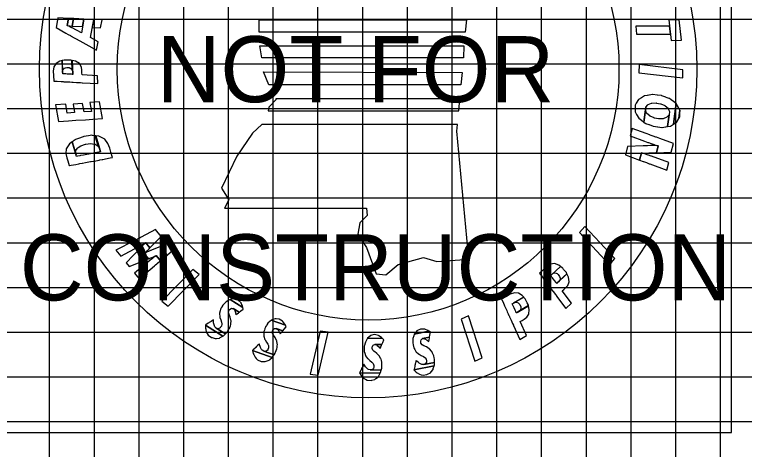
# Model space of a CAD drawing. Extents: x -10 to 342, y -5 to 215.
# Drawn here: x 313.22 to 329.53, y 185.38 to 195.1 of the extents above; entities that cross this region are included whole.
import ezdxf

# ---------------------------------------------------------------- set-up
doc = ezdxf.new("R2010")
doc.units = 0
for name, color, linetype in [('SHEET_LOGO', 7, 'Continuous'), ('SHEET_PRELIM', 7, 'Continuous'), ('XS_SHEET_MAJOR_GRIDS', 7, 'Continuous'), ('XS_SHEET_MEDIUM_GRIDS', 7, 'Continuous'), ('XS_SHEET_MINOR_GRIDS', 7, 'Continuous')]:
    doc.layers.add(name, color=color, linetype=linetype)

msp = doc.modelspace()

# ---------------------------------------------------------------- linework, layer by layer
at = {"layer": 'SHEET_LOGO'}
for points in [[(313, 185.757), (329.243, 185.757), (329.243, 202), (313, 202)], [(314.876, 194.399), (315.047, 194.303), (315.082, 194.491), (314.912, 194.587), (314.987, 194.989), (314.767, 194.998), (314.71, 194.693), (314.502, 194.803), (314.498, 194.804), (314.449, 194.828), (314.448, 194.829), (314.395, 194.852), (314.425, 195.013), (314.186, 195.024), (314.145, 194.808), (314.364, 194.686), (314.415, 194.657), (314.416, 194.656), (314.465, 194.629), (314.469, 194.627), (314.676, 194.511)], [(314.452, 194.845), (314.505, 194.841), (314.537, 195.008), (314.483, 195.011), (314.482, 195.011), (314.425, 195.013), (314.395, 194.852), (314.451, 194.845)], [(314.509, 194.841), (314.735, 194.829), (314.767, 194.998), (314.541, 195.008), (314.537, 195.008), (314.505, 194.841)], [(314.954, 194.813), (315.141, 194.805), (315.174, 194.981), (314.987, 194.989)], [(318.683, 194.979), (323.322, 194.979), (323.289, 194.708), (318.683, 194.708)], [(328.072, 194.985), (327.843, 194.985), (327.893, 194.523), (328.123, 194.524)], [(327.859, 194.839), (327.104, 194.837), (327.123, 194.661), (327.878, 194.663)], [(318.7, 194.404), (323.263, 194.404), (323.255, 194.133), (318.742, 194.133)], [(314.734, 193.576), (315.077, 193.558), (315.068, 193.732), (314.725, 193.751), (314.723, 193.798), (314.72, 193.853), (314.71, 193.927), (314.668, 194.002), (314.58, 194.055), (314.501, 194.074), (314.517, 193.762), (314.516, 193.762), (314.511, 193.762), (314.488, 193.764), (314.485, 193.764), (314.445, 193.766), (314.389, 193.769), (314.36, 193.771), (314.34, 193.772), (314.307, 193.774), (314.296, 193.774), (314.293, 193.774), (314.278, 194.069), (314.232, 194.059), (314.145, 194.006), (314.094, 193.931), (314.082, 193.834), (314.087, 193.737), (314.094, 193.611), (314.094, 193.611), (314.111, 193.61), (314.166, 193.607), (314.255, 193.602), (314.302, 193.6), (314.305, 193.6), (314.316, 193.599), (314.349, 193.597), (314.369, 193.596), (314.398, 193.595), (314.454, 193.592), (314.494, 193.589), (314.498, 193.589), (314.52, 193.588), (314.525, 193.588), (314.526, 193.588), (314.604, 193.583), (314.69, 193.579), (314.728, 193.577), (314.734, 193.576)], [(314.482, 193.893), (314.506, 193.859), (314.495, 194.076), (314.472, 194.082), (314.468, 194.083), (314.428, 194.083), (314.373, 194.083), (314.344, 194.083), (314.325, 194.079), (314.292, 194.072), (314.28, 194.069), (314.278, 194.069), (314.292, 193.806), (314.292, 193.839), (314.302, 193.873), (314.334, 193.904), (314.353, 193.909), (314.382, 193.917), (314.437, 193.913), (314.478, 193.894)], [(314.513, 193.819), (314.516, 193.779), (314.501, 194.074), (314.5, 194.075), (314.495, 194.076), (314.506, 193.859)], [(328.156, 193.866), (327.177, 193.98), (327.176, 193.8), (328.154, 193.686)], [(323.221, 193.802), (323.195, 193.532), (318.903, 193.532), (318.785, 193.819)], [(319.056, 193.218), (319.056, 193.193), (318.903, 193.032), (318.886, 192.947), (323.145, 192.947), (323.17, 193.218)], [(327.114, 193.116), (327.09, 193.073), (327.09, 192.925), (327.121, 192.869), (327.169, 192.782), (327.229, 192.737), (327.285, 192.694), (327.328, 193.03), (327.329, 193.03), (327.37, 193.081), (327.375, 193.087), (327.378, 193.088), (327.456, 193.119), (327.458, 193.119), (327.462, 193.119), (327.557, 193.124), (327.56, 193.123), (327.566, 193.122), (327.656, 193.106), (327.661, 193.105), (327.665, 193.103), (327.753, 193.064), (327.757, 193.062), (327.758, 193.061), (327.825, 193.005), (327.826, 193.004), (327.831, 192.993), (327.858, 192.932), (327.849, 192.861), (327.815, 192.596), (327.878, 192.606), (327.949, 192.648), (328.008, 193.108), (327.948, 193.153), (327.893, 193.195), (327.892, 193.195), (327.86, 193.22), (327.854, 193.222), (327.853, 193.222), (327.782, 193.249), (327.781, 193.249), (327.777, 193.251), (327.689, 193.284), (327.684, 193.285), (327.679, 193.287), (327.588, 193.298), (327.583, 193.299), (327.58, 193.299), (327.487, 193.31), (327.483, 193.311), (327.481, 193.31), (327.405, 193.299), (327.403, 193.299), (327.398, 193.298), (327.363, 193.293), (327.362, 193.292), (327.3, 193.283), (327.229, 193.241), (327.164, 193.203)], [(314.964, 192.759), (315.182, 192.774), (315.118, 193.147), (314.899, 193.133), (314.934, 192.932), (314.77, 192.922), (314.738, 193.108), (314.525, 193.095), (314.557, 192.908), (314.396, 192.898), (314.362, 193.098), (314.135, 193.083), (314.2, 192.71), (314.426, 192.725), (314.587, 192.735), (314.8, 192.749)], [(327.32, 192.959), (327.328, 193.03), (327.285, 192.694), (327.285, 192.694)], [(328.056, 193.022), (328.008, 193.108), (327.949, 192.648), (328.013, 192.686), (328.063, 192.773), (328.088, 192.964)], [(327.347, 192.899), (327.32, 192.959), (327.285, 192.694), (327.317, 192.67), (327.321, 192.668), (327.323, 192.667), (327.394, 192.641), (327.396, 192.64), (327.396, 192.64), (327.4, 192.639), (327.49, 192.605), (327.493, 192.604), (327.498, 192.602), (327.589, 192.591), (327.594, 192.59), (327.599, 192.59), (327.69, 192.578), (327.694, 192.578), (327.695, 192.578), (327.771, 192.59), (327.772, 192.59), (327.779, 192.591), (327.815, 192.596), (327.815, 192.596), (327.849, 192.861), (327.849, 192.861), (327.808, 192.814), (327.8, 192.805), (327.799, 192.804), (327.72, 192.771), (327.719, 192.771), (327.715, 192.771), (327.622, 192.766), (327.617, 192.767), (327.612, 192.768), (327.522, 192.785), (327.517, 192.786), (327.514, 192.788), (327.424, 192.828), (327.421, 192.83), (327.419, 192.832), (327.352, 192.888), (327.35, 192.892)], [(328.088, 192.815), (328.088, 192.964), (328.063, 192.773), (328.088, 192.815)], [(318.742, 192.643), (318.539, 192.448), (318.184, 191.932), (317.845, 191.22), (318.006, 190.958), (317.913, 190.772), (321.087, 190.772), (321.096, 190.611), (320.935, 190.442), (320.893, 190.188), (321.087, 189.891), (321.299, 189.307), (321.519, 189.282), (321.79, 189.51), (322.357, 189.671), (322.654, 189.578), (323.373, 189.629), (323.102, 192.49), (323.119, 192.643)], [(327.34, 192.438), (327.023, 192.555), (326.98, 192.385), (327.297, 192.27), (327.297, 192.27), (327.375, 192.242), (327.385, 192.238), (327.448, 192.216), (327.451, 192.215), (327.514, 192.193), (327.524, 192.19), (327.604, 192.168), (327.564, 192.01), (327.898, 192.02), (327.947, 192.214), (327.644, 192.326), (327.566, 192.355), (327.556, 192.359), (327.493, 192.382), (327.49, 192.383), (327.428, 192.406), (327.418, 192.41)], [(315.405, 191.902), (315.406, 191.902), (315.37, 192.024), (315.343, 192.113), (315.305, 192.215), (315.231, 192.314), (315.102, 192.379), (315.035, 192.388), (315.141, 192.032), (315.141, 192.031), (315.126, 192.029), (315.075, 192.019), (315.056, 192.015), (314.981, 192.001), (314.878, 191.982), (314.867, 191.98), (314.756, 191.959), (314.69, 191.946), (314.676, 191.944), (314.625, 191.934), (314.605, 191.93), (314.602, 191.93), (314.506, 192.253), (314.448, 192.213), (314.374, 192.101), (314.365, 191.996), (314.387, 191.895), (314.406, 191.83), (314.438, 191.723), (314.438, 191.723), (314.445, 191.724), (314.484, 191.731), (314.586, 191.75), (314.652, 191.762), (314.655, 191.763), (314.675, 191.767), (314.726, 191.776), (314.739, 191.778), (314.806, 191.791), (314.917, 191.811), (314.928, 191.813), (315.031, 191.833), (315.106, 191.846), (315.125, 191.85), (315.177, 191.86), (315.191, 191.862), (315.191, 191.862), (315.252, 191.874), (315.356, 191.893), (315.398, 191.901)], [(315.021, 192.201), (315.088, 192.157), (315.019, 192.39), (314.962, 192.397), (314.941, 192.4), (314.866, 192.388), (314.762, 192.372), (314.751, 192.368), (314.645, 192.33), (314.582, 192.307), (314.57, 192.298), (314.526, 192.267), (314.526, 192.267), (314.509, 192.255), (314.506, 192.253), (314.593, 191.962), (314.581, 192.01), (314.587, 192.063), (314.624, 192.116), (314.637, 192.124), (314.695, 192.163), (314.801, 192.2), (314.813, 192.202), (314.917, 192.216), (315, 192.204)], [(315.088, 192.157), (315.122, 192.094), (315.035, 192.388), (315.019, 192.39)], [(315.122, 192.094), (315.141, 192.032), (315.035, 192.388), (315.035, 192.388)], [(327.27, 192.164), (326.921, 192.15), (326.873, 191.963), (327.19, 191.846), (327.231, 192.007), (327.315, 192.003), (327.326, 192.002), (327.395, 192.004), (327.398, 192.005), (327.467, 192.007), (327.478, 192.007), (327.564, 192.01), (327.604, 192.168), (327.52, 192.172), (327.509, 192.172), (327.44, 192.17), (327.437, 192.17), (327.368, 192.168), (327.356, 192.167)], [(327.31, 191.985), (327.231, 192.007), (327.19, 191.846), (327.268, 191.817), (327.278, 191.814), (327.341, 191.79), (327.344, 191.789), (327.406, 191.766), (327.416, 191.763), (327.797, 191.622), (327.84, 191.792), (327.459, 191.932), (327.449, 191.936), (327.386, 191.959), (327.383, 191.96), (327.321, 191.982)], [(315.889, 190.04), (315.484, 189.829), (315.592, 189.697), (315.993, 189.911), (316.012, 189.921), (316.018, 189.925), (316.018, 189.925), (316.02, 189.926), (316.02, 189.926), (316.058, 189.947), (316.065, 189.951), (316.076, 189.958), (316.079, 189.96), (316.08, 189.96), (316.081, 189.961), (316.122, 189.987), (316.127, 189.989), (316.146, 190.001), (316.242, 189.882), (316.493, 190.14), (316.371, 190.291), (316.047, 190.122), (316.027, 190.112), (316.023, 190.109), (315.979, 190.087), (315.978, 190.086), (315.977, 190.086), (315.974, 190.084), (315.962, 190.078), (315.955, 190.074), (315.916, 190.054), (315.914, 190.053), (315.908, 190.05)], [(325.844, 190.229), (326.515, 189.507), (326.633, 189.643), (325.962, 190.364)], [(316.022, 189.876), (315.712, 189.549), (315.779, 189.466), (316.214, 189.639), (316.117, 189.759), (316.132, 189.773), (316.137, 189.778), (316.139, 189.78), (316.17, 189.809), (316.176, 189.815), (316.185, 189.824), (316.187, 189.826), (316.188, 189.827), (316.189, 189.828), (316.223, 189.863), (316.227, 189.866), (316.242, 189.882), (316.146, 190.001), (316.13, 189.986), (316.126, 189.982), (316.092, 189.948), (316.091, 189.947), (316.09, 189.946), (316.088, 189.944), (316.078, 189.934), (316.073, 189.929), (316.043, 189.898), (316.041, 189.896), (316.036, 189.891)], [(316.136, 189.768), (316.117, 189.759), (316.214, 189.639), (316.235, 189.647), (316.235, 189.647), (316.241, 189.65), (316.244, 189.651), (316.285, 189.668), (316.293, 189.67), (316.293, 189.671), (316.306, 189.676), (316.306, 189.676), (316.309, 189.677), (316.31, 189.677), (316.311, 189.678), (316.311, 189.678), (316.356, 189.699), (316.361, 189.701), (316.381, 189.711), (316.476, 189.595), (316.75, 189.825), (316.627, 189.975), (316.281, 189.834), (316.26, 189.825), (316.255, 189.823), (316.209, 189.804), (316.208, 189.803), (316.207, 189.802), (316.204, 189.801), (316.191, 189.796), (316.184, 189.793), (316.145, 189.773), (316.142, 189.772)], [(316.243, 189.604), (315.898, 189.32), (316, 189.195), (316.342, 189.482), (316.358, 189.496), (316.363, 189.5), (316.365, 189.502), (316.365, 189.502), (316.398, 189.529), (316.404, 189.534), (316.414, 189.543), (316.416, 189.545), (316.417, 189.546), (316.418, 189.546), (316.455, 189.577), (316.459, 189.581), (316.476, 189.595), (316.381, 189.711), (316.364, 189.698), (316.36, 189.695), (316.321, 189.666), (316.32, 189.665), (316.319, 189.664), (316.317, 189.662), (316.306, 189.654), (316.3, 189.649), (316.267, 189.623), (316.265, 189.621), (316.259, 189.617)], [(325.333, 188.803), (325.538, 188.527), (325.666, 188.646), (325.461, 188.921), (325.496, 188.953), (325.536, 188.991), (325.587, 189.046), (325.617, 189.126), (325.602, 189.228), (325.566, 189.301), (325.337, 189.089), (325.336, 189.089), (325.333, 189.093), (325.32, 189.111), (325.318, 189.114), (325.294, 189.146), (325.26, 189.191), (325.243, 189.214), (325.231, 189.23), (325.211, 189.257), (325.204, 189.266), (325.203, 189.268), (325.42, 189.468), (325.382, 189.498), (325.287, 189.531), (325.196, 189.522), (325.114, 189.468), (325.042, 189.403), (324.95, 189.317), (324.95, 189.317), (324.96, 189.303), (324.993, 189.259), (325.047, 189.187), (325.075, 189.15), (325.076, 189.148), (325.083, 189.139), (325.103, 189.112), (325.115, 189.096), (325.132, 189.072), (325.165, 189.028), (325.189, 188.996), (325.191, 188.993), (325.205, 188.975), (325.208, 188.97), (325.208, 188.97), (325.255, 188.907), (325.306, 188.838), (325.329, 188.808), (325.333, 188.803)], [(325.415, 189.199), (325.404, 189.159), (325.564, 189.306), (325.554, 189.327), (325.552, 189.331), (325.526, 189.362), (325.491, 189.404), (325.473, 189.427), (325.457, 189.439), (325.431, 189.46), (325.421, 189.467), (325.42, 189.468), (325.226, 189.29), (325.252, 189.31), (325.284, 189.324), (325.328, 189.32), (325.345, 189.308), (325.369, 189.291), (325.402, 189.247), (325.414, 189.203)], [(317.201, 189.398), (316.511, 188.695), (316.652, 188.583), (317.342, 189.286)], [(325.378, 189.128), (325.349, 189.1), (325.566, 189.301), (325.566, 189.301), (325.564, 189.306), (325.404, 189.159)], [(324.369, 188.15), (324.51, 187.837), (324.661, 187.925), (324.52, 188.238), (324.561, 188.262), (324.608, 188.29), (324.67, 188.333), (324.716, 188.404), (324.724, 188.507), (324.705, 188.586), (324.434, 188.429), (324.434, 188.429), (324.432, 188.434), (324.423, 188.454), (324.421, 188.458), (324.405, 188.494), (324.382, 188.545), (324.37, 188.571), (324.362, 188.59), (324.348, 188.62), (324.344, 188.631), (324.343, 188.633), (324.598, 188.781), (324.568, 188.818), (324.481, 188.871), (324.391, 188.882), (324.299, 188.847), (324.215, 188.799), (324.106, 188.735), (324.106, 188.735), (324.113, 188.72), (324.136, 188.669), (324.173, 188.588), (324.192, 188.545), (324.193, 188.543), (324.198, 188.532), (324.211, 188.502), (324.219, 188.483), (324.231, 188.457), (324.254, 188.406), (324.27, 188.37), (324.272, 188.366), (324.281, 188.346), (324.283, 188.341), (324.284, 188.341), (324.316, 188.269), (324.351, 188.191), (324.367, 188.156), (324.369, 188.15)], [(324.534, 188.519), (324.516, 188.483), (324.703, 188.592), (324.698, 188.615), (324.697, 188.618), (324.679, 188.654), (324.654, 188.703), (324.641, 188.729), (324.628, 188.745), (324.606, 188.77), (324.599, 188.78), (324.598, 188.781), (324.37, 188.649), (324.4, 188.663), (324.434, 188.67), (324.476, 188.656), (324.49, 188.641), (324.51, 188.619), (324.532, 188.569), (324.534, 188.523)], [(317.772, 188.074), (317.722, 188.09), (317.929, 187.96), (317.939, 187.969), (317.944, 187.975), (317.96, 187.989), (317.966, 187.999), (317.975, 188.013), (317.995, 188.043), (318.017, 188.076), (318.021, 188.081), (318.03, 188.107), (318.042, 188.14), (318.054, 188.173), (318.055, 188.184), (318.056, 188.255), (318.054, 188.264), (318.036, 188.334), (318.013, 188.395), (318.013, 188.397), (318.002, 188.439), (318.007, 188.479), (318.009, 188.483), (318.028, 188.509), (318.028, 188.509), (318.029, 188.511), (318.033, 188.514), (318.065, 188.533), (318.079, 188.531), (318.079, 188.531), (318.104, 188.529), (318.238, 188.444), (318.278, 188.474), (318.328, 188.51), (318.32, 188.553), (318.038, 188.73), (318.007, 188.712), (317.95, 188.68), (317.917, 188.646), (317.909, 188.639), (317.904, 188.634), (317.88, 188.61), (317.877, 188.607), (317.875, 188.605), (317.859, 188.577), (317.856, 188.573), (317.837, 188.543), (317.822, 188.517), (317.821, 188.516), (317.81, 188.476), (317.797, 188.425), (317.797, 188.417), (317.803, 188.342), (317.808, 188.328), (317.825, 188.276), (317.843, 188.224), (317.851, 188.188), (317.853, 188.18), (317.845, 188.137), (317.824, 188.108), (317.814, 188.095), (317.801, 188.089), (317.78, 188.078)], [(318.07, 188.734), (318.038, 188.73), (318.32, 188.553), (318.314, 188.581), (318.283, 188.646), (318.279, 188.655), (318.214, 188.716), (318.214, 188.716), (318.15, 188.736), (318.13, 188.742)], [(318.155, 188.429), (318.161, 188.387), (318.189, 188.408), (318.191, 188.409), (318.194, 188.412), (318.223, 188.433), (318.229, 188.437), (318.229, 188.437), (318.238, 188.444), (318.103, 188.529), (318.135, 188.497), (318.138, 188.487), (318.154, 188.437), (318.154, 188.432)], [(324.484, 188.458), (324.449, 188.437), (324.705, 188.586), (324.705, 188.586), (324.703, 188.592), (324.516, 188.483)], [(318.987, 188.279), (318.956, 188.268), (319.27, 188.156), (319.259, 188.182), (319.214, 188.238), (319.208, 188.246), (319.131, 188.292), (319.131, 188.292), (319.065, 188.298), (319.044, 188.299)], [(323.2, 188.29), (323.503, 187.353), (323.668, 187.426), (323.364, 188.363)], [(317.496, 188.167), (317.482, 188.158), (317.873, 187.911), (317.889, 187.92), (317.929, 187.96), (317.722, 188.09), (317.697, 188.121), (317.683, 188.139), (317.676, 188.167), (317.672, 188.184), (317.667, 188.207), (317.665, 188.25), (317.663, 188.275), (317.645, 188.263), (317.612, 188.241), (317.597, 188.232), (317.585, 188.225), (317.566, 188.212), (317.56, 188.208), (317.547, 188.2)], [(317.547, 187.93), (317.618, 187.881), (317.631, 187.877), (317.702, 187.856), (317.729, 187.859), (317.798, 187.868), (317.816, 187.879), (317.873, 187.911), (317.482, 188.157), (317.483, 188.088), (317.489, 188.063), (317.503, 188.002), (317.523, 187.968)], [(318.839, 187.57), (318.787, 187.574), (319.017, 187.492), (319.024, 187.503), (319.029, 187.51), (319.04, 187.527), (319.044, 187.539), (319.05, 187.554), (319.063, 187.587), (319.078, 187.625), (319.08, 187.63), (319.084, 187.658), (319.089, 187.692), (319.093, 187.727), (319.091, 187.738), (319.077, 187.807), (319.073, 187.816), (319.041, 187.881), (319.005, 187.935), (319.004, 187.937), (318.984, 187.976), (318.98, 188.016), (318.982, 188.02), (318.994, 188.05), (318.994, 188.05), (318.995, 188.052), (318.998, 188.055), (319.026, 188.081), (319.04, 188.083), (319.04, 188.083), (319.064, 188.085), (319.214, 188.032), (319.247, 188.069), (319.287, 188.116), (319.27, 188.156), (318.956, 188.268), (318.93, 188.244), (318.882, 188.2), (318.856, 188.16), (318.85, 188.15), (318.847, 188.145), (318.829, 188.116), (318.827, 188.113), (318.825, 188.11), (318.815, 188.08), (318.813, 188.076), (318.801, 188.041), (318.792, 188.013), (318.791, 188.012), (318.789, 187.971), (318.787, 187.918), (318.789, 187.91), (318.811, 187.838), (318.819, 187.825), (318.847, 187.779), (318.876, 187.732), (318.891, 187.698), (318.895, 187.69), (318.896, 187.647), (318.882, 187.614), (318.875, 187.599), (318.864, 187.59), (318.845, 187.575)], [(319.136, 187.999), (319.151, 187.96), (319.174, 187.986), (319.175, 187.988), (319.178, 187.991), (319.202, 188.018), (319.206, 188.023), (319.206, 188.023), (319.214, 188.032), (319.064, 188.085), (319.102, 188.061), (319.107, 188.052), (319.133, 188.007), (319.135, 188.002)], [(320.048, 188.021), (319.823, 187.063), (320.001, 187.04), (320.227, 187.999)], [(322.411, 187.297), (322.365, 187.274), (322.604, 187.323), (322.605, 187.337), (322.605, 187.344), (322.606, 187.366), (322.604, 187.377), (322.601, 187.393), (322.595, 187.429), (322.588, 187.468), (322.587, 187.474), (322.576, 187.499), (322.562, 187.532), (322.548, 187.564), (322.54, 187.572), (322.492, 187.624), (322.484, 187.629), (322.423, 187.668), (322.364, 187.696), (322.363, 187.697), (322.326, 187.72), (322.302, 187.752), (322.301, 187.757), (322.296, 187.788), (322.296, 187.788), (322.295, 187.791), (322.297, 187.795), (322.307, 187.831), (322.318, 187.84), (322.318, 187.84), (322.337, 187.855), (322.493, 187.887), (322.501, 187.936), (322.512, 187.997), (322.477, 188.022), (322.15, 187.955), (322.14, 187.921), (322.122, 187.858), (322.121, 187.811), (322.121, 187.8), (322.121, 187.794), (322.12, 187.759), (322.12, 187.755), (322.12, 187.753), (322.127, 187.721), (322.128, 187.717), (322.135, 187.681), (322.142, 187.652), (322.142, 187.651), (322.162, 187.615), (322.187, 187.568), (322.193, 187.563), (322.249, 187.512), (322.262, 187.505), (322.31, 187.48), (322.359, 187.455), (322.39, 187.434), (322.397, 187.429), (322.421, 187.393), (322.425, 187.358), (322.428, 187.341), (322.423, 187.328), (322.414, 187.306)], [(322.171, 187.98), (322.151, 187.955), (322.477, 188.022), (322.454, 188.038), (322.386, 188.064), (322.377, 188.067), (322.288, 188.067), (322.288, 188.067), (322.228, 188.037), (322.209, 188.028)], [(321.22, 187.167), (321.17, 187.154), (321.414, 187.15), (321.417, 187.164), (321.419, 187.171), (321.425, 187.191), (321.425, 187.203), (321.426, 187.22), (321.427, 187.255), (321.429, 187.296), (321.429, 187.302), (321.424, 187.329), (321.417, 187.363), (321.411, 187.397), (321.405, 187.407), (321.37, 187.468), (321.363, 187.475), (321.312, 187.526), (321.26, 187.566), (321.259, 187.567), (321.228, 187.598), (321.211, 187.635), (321.211, 187.639), (321.213, 187.671), (321.213, 187.671), (321.214, 187.674), (321.216, 187.678), (321.233, 187.711), (321.246, 187.717), (321.246, 187.717), (321.268, 187.727), (321.427, 187.725), (321.446, 187.771), (321.47, 187.828), (321.44, 187.86), (321.107, 187.866), (321.09, 187.834), (321.059, 187.777), (321.047, 187.731), (321.045, 187.72), (321.043, 187.714), (321.035, 187.681), (321.034, 187.677), (321.034, 187.674), (321.034, 187.642), (321.034, 187.638), (321.033, 187.601), (321.033, 187.571), (321.033, 187.57), (321.045, 187.531), (321.059, 187.48), (321.064, 187.473), (321.108, 187.412), (321.12, 187.402), (321.161, 187.367), (321.203, 187.332), (321.229, 187.305), (321.235, 187.299), (321.25, 187.258), (321.247, 187.223), (321.245, 187.206), (321.238, 187.195), (321.225, 187.174)], [(321.133, 187.886), (321.108, 187.866), (321.44, 187.86), (321.422, 187.881), (321.361, 187.921), (321.352, 187.926), (321.266, 187.945), (321.265, 187.945), (321.201, 187.929), (321.18, 187.924)], [(322.443, 187.819), (322.477, 187.792), (322.482, 187.827), (322.483, 187.829), (322.484, 187.833), (322.49, 187.869), (322.491, 187.876), (322.491, 187.876), (322.493, 187.887), (322.337, 187.855), (322.382, 187.853), (322.391, 187.849), (322.437, 187.824), (322.441, 187.821)], [(318.549, 187.601), (318.538, 187.589), (318.973, 187.433), (318.986, 187.445), (319.017, 187.492), (318.787, 187.574), (318.755, 187.6), (318.738, 187.614), (318.725, 187.64), (318.718, 187.656), (318.708, 187.676), (318.696, 187.719), (318.689, 187.742), (318.674, 187.727), (318.646, 187.698), (318.633, 187.686), (318.624, 187.676), (318.608, 187.66), (318.602, 187.654), (318.592, 187.644)], [(321.364, 187.669), (321.391, 187.636), (321.404, 187.668), (321.405, 187.671), (321.406, 187.674), (321.42, 187.708), (321.423, 187.714), (321.423, 187.714), (321.427, 187.725), (321.268, 187.727), (321.312, 187.716), (321.319, 187.71), (321.359, 187.675), (321.362, 187.671)], [(318.65, 187.38), (318.73, 187.347), (318.744, 187.347), (318.818, 187.341), (318.843, 187.351), (318.909, 187.375), (318.924, 187.388), (318.973, 187.433), (318.538, 187.588), (318.554, 187.52), (318.565, 187.498), (318.592, 187.441), (318.619, 187.413)], [(322.148, 187.174), (322.144, 187.157), (322.597, 187.25), (322.602, 187.266), (322.604, 187.323), (322.365, 187.274), (322.325, 187.28), (322.303, 187.283), (322.278, 187.299), (322.264, 187.308), (322.244, 187.321), (322.212, 187.351), (322.194, 187.367), (322.189, 187.346), (322.18, 187.307), (322.176, 187.29), (322.173, 187.277), (322.167, 187.255), (322.166, 187.247), (322.162, 187.233)], [(320.936, 187.103), (320.929, 187.088), (321.391, 187.08), (321.4, 187.095), (321.414, 187.15), (321.17, 187.154), (321.132, 187.168), (321.111, 187.176), (321.09, 187.197), (321.078, 187.209), (321.062, 187.226), (321.037, 187.262), (321.023, 187.282), (321.014, 187.262), (320.996, 187.227), (320.988, 187.211), (320.983, 187.199), (320.973, 187.178), (320.969, 187.171), (320.963, 187.158)], [(322.349, 187.037), (322.434, 187.051), (322.446, 187.057), (322.512, 187.091), (322.529, 187.112), (322.572, 187.167), (322.578, 187.186), (322.597, 187.25), (322.144, 187.157), (322.193, 187.108), (322.214, 187.094), (322.267, 187.059), (322.305, 187.049)], [(321.103, 186.926), (321.188, 186.921), (321.202, 186.925), (321.274, 186.944), (321.295, 186.961), (321.349, 187.004), (321.359, 187.022), (321.391, 187.08), (320.929, 187.088), (320.966, 187.029), (320.984, 187.01), (321.028, 186.965), (321.062, 186.947)]]:
    msp.add_lwpolyline(points, close=True, dxfattribs=at)
for radius in [7.347, 5.608]:
    msp.add_circle((321.121, 193.879), radius, dxfattribs=at)
at = {"layer": 'SHEET_PRELIM'}
msp.add_lwpolyline([(313, 185.757), (329.243, 185.757), (329.243, 202), (313, 202)], close=True, dxfattribs=at)
at = {"layer": 'XS_SHEET_MAJOR_GRIDS'}
for p, q in [((320, 0), (320, 202)), ((5, 190), (340, 190))]:
    msp.add_line(p, q, dxfattribs=at)
at = {"layer": 'XS_SHEET_MEDIUM_GRIDS'}
for p, q in [((315, 0), (315, 202)), ((325, 0), (325, 202)), ((5, 195), (340, 195))]:
    msp.add_line(p, q, dxfattribs=at)
at = {"layer": 'XS_SHEET_MINOR_GRIDS'}
for p, q in [((314, 0), (314, 202)), ((316, 0), (316, 202)), ((317, 0), (317, 202)), ((318, 0), (318, 202)), ((319, 0), (319, 202)), ((321, 0), (321, 202)), ((322, 0), (322, 202)), ((323, 0), (323, 202)), ((324, 0), (324, 202)), ((326, 0), (326, 202)), ((327, 0), (327, 202)), ((328, 0), (328, 202)), ((329, 0), (329, 202)), ((5, 194), (340, 194)), ((5, 193), (340, 193)), ((5, 192), (340, 192)), ((5, 191), (340, 191)), ((5, 189), (340, 189)), ((5, 188), (340, 188)), ((5, 187), (340, 187)), ((5, 186), (340, 186))]:
    msp.add_line(p, q, dxfattribs=at)

# ---------------------------------------------------------------- texts
at = {"layer": 'SHEET_PRELIM'}
for s, height, p in [('NOT FOR', 1.4766, (316.396, 193.14)), ('CONSTRUCTION', 1.47661, (313.335, 188.71))]:
    msp.add_text(s, height=height, dxfattribs=at).set_placement(p)

doc.saveas('drawing.dxf')
